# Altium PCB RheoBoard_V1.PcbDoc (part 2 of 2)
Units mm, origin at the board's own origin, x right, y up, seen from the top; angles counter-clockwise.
Board outline 146 x 88.34 mm, 2 copper layers (Top Layer, Bottom Layer); 132 components, 71 nets, 340 pads, 144 vias.
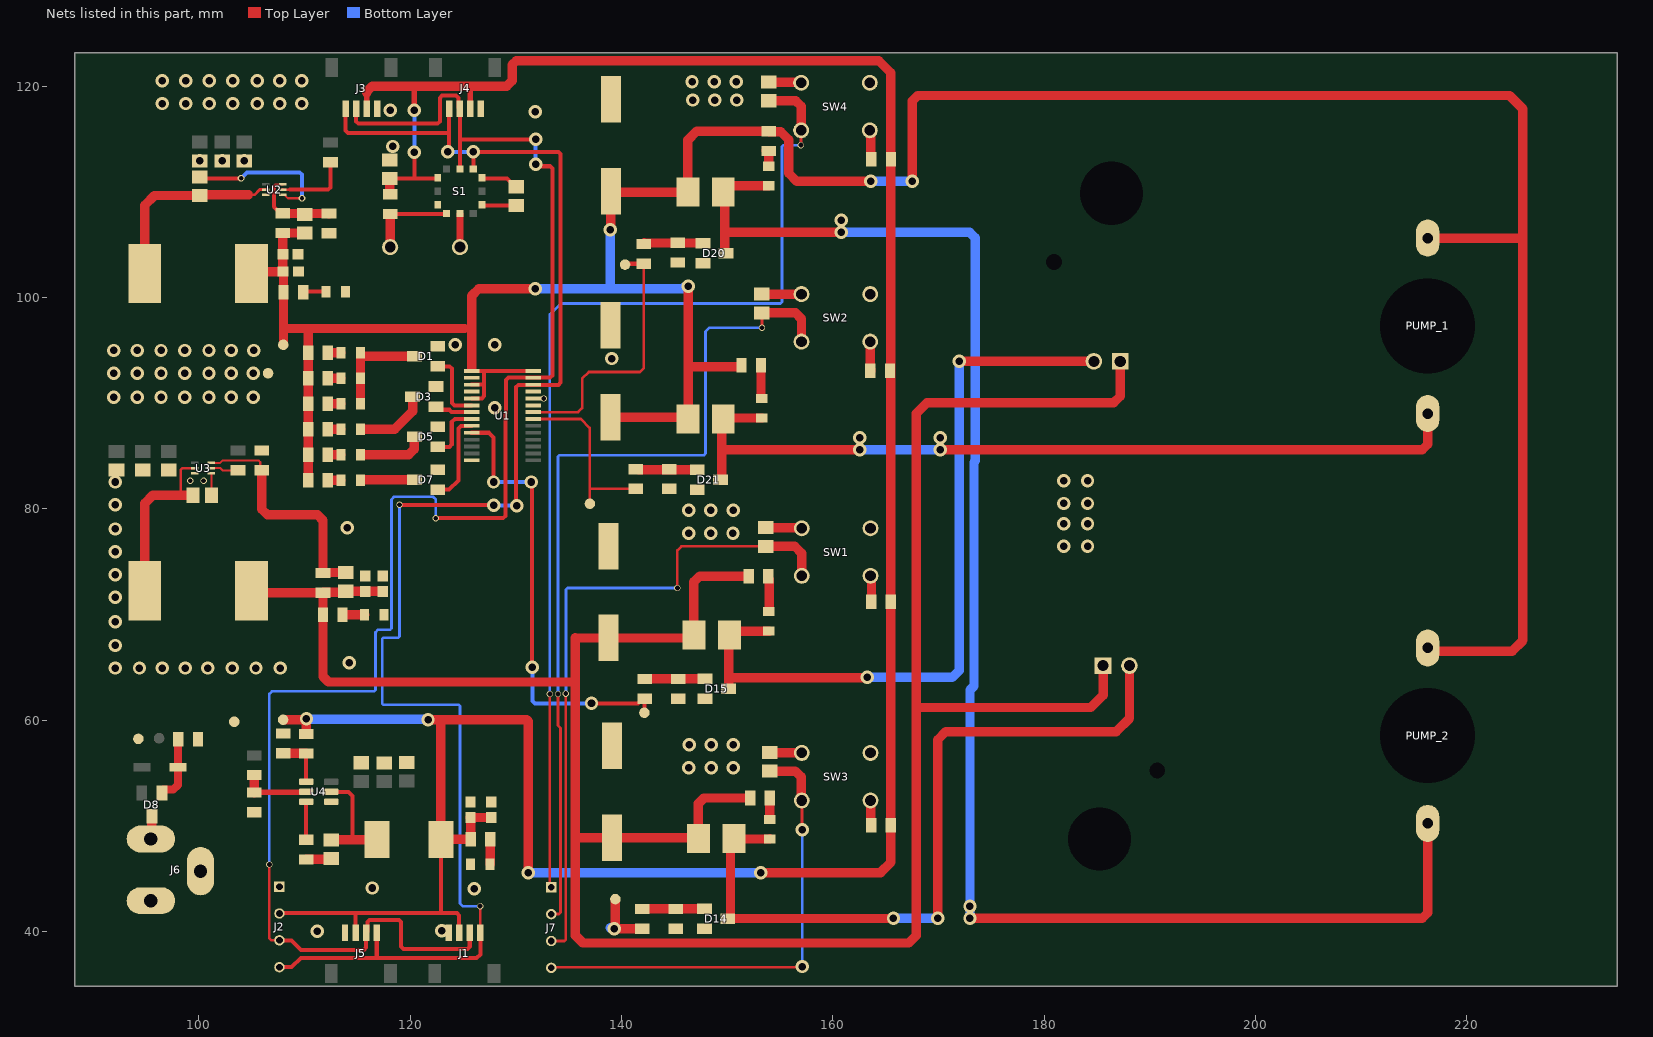
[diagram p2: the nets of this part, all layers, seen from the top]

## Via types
v1: diameter 1.27, hole 0.711, Top Layer to Bottom Layer, tented both sides, 129 vias
v2: diameter 0.6, hole 0.45, Top Layer to Bottom Layer, tented both sides, 13 vias
v3: diameter 0.65, hole 0.4, Top Layer to Bottom Layer, tented both sides, 2 vias

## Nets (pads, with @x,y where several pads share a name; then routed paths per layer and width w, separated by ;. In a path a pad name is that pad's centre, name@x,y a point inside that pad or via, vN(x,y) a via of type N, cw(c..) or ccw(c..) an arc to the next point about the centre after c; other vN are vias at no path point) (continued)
GND: C3.2 C7.1 C8.1 C9.1 C10.1 C11.1 C12.1 C15.1 C16.1 C17.1 C18.1 C22.1 C23.1 C24.1 C25.1 C26.1 C28.2 C29.2 C30.2 C31.2 D1.2 D3.2 D5.2 D7.2 D14.2 D15.2 D20.2 D21.2 GND.1 J1.1 J2.01 J3.1 J4.1 J5.1 J6.2 J6.3 lLED1.1 lLED2.1 lLED3.1 R19.2 R20.1 R27.1 R28.1 R33.1 R34.1 R39.1 R40.1 R41.1 S1.10 SW1.3 SW2.3 SW3.3 SW4.3 U1.2 U1.4 U1.14 U1.23 U1.24 U1.25 U2.3 U3.3 U4.1
  other v1: 111.227,40.03 122.987,40.081 126.06,44.069 116.395,44.133 146.38,55.524 148.476,55.524 150.571,55.524 146.393,57.683 148.488,57.683 150.584,57.683 92.1,64.948 94.386,64.948 96.545,64.948 98.704,64.948 100.863,64.948 103.149,64.948 105.41,64.948 107.696,64.948 114.224,65.43 92.075,67.081 92.075,69.342 92.075,71.628 92.075,73.787 92.075,75.946 181.864,76.454 184.095,76.454 146.355,77.699 148.45,77.699 150.546,77.699 92.075,78.105 114.046,78.232 181.864,78.613 184.095,78.613 146.368,79.858 148.463,79.858 150.558,79.858 92.075,80.391 181.864,80.518 184.095,80.518 92.075,82.55 181.864,82.677 184.095,82.677 127.991,89.586 91.965,90.551 94.196,90.551 96.427,90.551 98.658,90.551 100.965,90.551 103.075,90.551 105.156,90.551 91.965,92.837 94.196,92.837 96.427,92.837 98.658,92.837 100.965,92.837 103.075,92.837 105.156,92.837 139.065,94.234 91.965,94.996 94.196,94.996 96.427,94.996 98.658,94.996 100.965,94.996 103.075,94.996 105.185,94.996 124.282,95.529 127.991,95.529 100.09,112.939 102.2,112.939 104.31,112.939 118.364,114.3 131.826,117.602 118.11,117.729 96.537,118.364 98.768,118.364 100.999,118.364 103.23,118.364 105.537,118.364 107.647,118.364 109.757,118.364 146.723,118.694 148.819,118.694 150.914,118.694 146.672,120.421 148.768,120.421 150.863,120.421 96.537,120.523 98.768,120.523 100.999,120.523 103.23,120.523 105.537,120.523 107.647,120.523 109.757,120.523
  other v2: 99.187,82.677 100.457,82.677 132.639,90.449
Net3V3_1: 3V3.1 C3.1 C25.2 C26.2 J1.2 J2.02 J3.2 J4.2 J5.2 L3.2 R1.2 R2.2 R6.2 R7.2 R8.2 R25.2 R26.2 S1.12 | length 264.4
  Top Layer w0.381: J2.02@107.63,41.72 107.68,41.77 122.86,41.77 ; J5.2@114.84,39.903 114.84,41.656 ; C3.1@118.06,111.265 118.073,111.252 120.396,111.252 ; v1(120.396,113.767) 120.396,111.252 ; S1.12@122.614,111.252 120.396,111.252 ; L3.2@122.92,48.7 122.92,41.83 122.86,41.77 ; J1.2@124.64,39.903 124.64,41.547 124.417,41.77 122.86,41.77
  Top Layer w0.508: J3.2@115.89,117.88 115.89,119.38 ; v1(120.396,117.729) 120.396,119.888 ; J4.2@125.69,117.88 125.69,119.698 ; 130.048,122.555 130.054,122.549 130.054,122.415
  Top Layer w0.889: 3V3.1@107.975,60.046 107.997,60.067 110.122,60.067 v1@110.18,60.124 ; R26.2@110.169,58.709 110.18,58.72 v1@110.18,60.124 ; v1(110.19,60.134) v1@110.18,60.124 ; 115.89,119.38 115.89,119.494 116.411,120.015 129.146,120.015 129.667,120.536 129.667,122.047 130.035,122.415 130.054,122.415 164.35,122.415 165.48,121.285 165.48,113.12 165.487,113.113 165.487,71.237 R1.2@165.48,71.23 R7.2@165.48,50.07 165.48,46.557 164.516,45.593 v1(153.162,45.593) ; R6.2@118.06,109.982 C3.1@118.06,111.265 ; v1(121.691,60.071) 122.936,60.071 ; C25.2@125.67,50.804 125.67,50.769 125.725,50.714 R25.2@125.725,48.731 122.951,48.731 L3.2@122.92,48.7 122.911,48.709 122.911,60.046 122.936,60.071 ; C25.2@125.72,50.804 125.722,50.802 127.669,50.802 C26.2@127.671,50.799 ; v1(131.191,45.593) 131.191,59.893 131.013,60.071 122.936,60.071
  Bottom Layer w0.381: v1(120.396,113.767) v1(120.396,117.729)
  Bottom Layer w0.889: v1(110.19,60.134) 110.222,60.103 v1@121.66,60.103 ; v1(131.191,45.593) v1(153.162,45.593)
Net4V5_1: 4V5.1 C13.2 C15.2 C16.2 C30.1 C31.1 D18.2 D19.2 L1.1 PUMP_1.1 PUMP_2.1 R9.2 R10.2 R11.2 R12.2 R13.1 R14.1 R15.1 R16.2 R35.1 R36.1 U1.1 U1.3 U1.5 U1.28 | length 292.3
  Top Layer w0.381: U1.3@125.824,91.756 126.981,91.756 127.005,91.78 ; U1.1@125.824,93.051 U1.28@131.666,93.051 ; U1.5@125.837,90.473 126.788,90.473 127.005,90.69 127.005,91.78 ; 127.005,92.921 127.005,91.78
  Top Layer w0.889: L1.1@104.98,102.28 105.16,102.46 C16.2@107.964,102.46 ; R16.2@107.96,106.11 107.962,106.108 107.962,102.462 107.978,102.462 108.02,102.419 R12.2@108.02,100.51 108.02,95.549 4V5.1@108.001,95.529 ; R16.2@107.962,106.107 110.008,106.107 C13.2@110.01,106.105 ; 108.153,97.07 110.363,97.07 ; R15.1@110.349,82.72 R14.1@110.349,85.133 R13.1@110.349,87.546 R9.2@110.349,89.959 R10.2@110.349,92.372 R11.2@110.349,94.785 110.349,97.056 110.363,97.07 ; 125.16,97.07 110.363,97.07 ; 125.84,93.3 125.84,100.186 126.492,100.838 v1(131.826,100.838) ; v1(138.938,106.426) 138.969,106.457 138.969,110.014 C30.1@139,110.045 ; C30.1@138.938,109.745 139.175,109.982 D19.2@146.278,109.982 146.278,114.909 147.107,115.738 153.756,115.738 153.797,115.779 153.838,115.738 R35.1@153.924,115.738 153.965,115.698 155.072,115.698 155.829,114.94 155.829,111.76 156.591,110.998 v1(163.576,110.998) ; C31.1@138.94,88.69 146.096,88.69 D18.2@146.278,88.508 ; D18.2@146.304,88.599 v1(146.304,101.092) ; 146.431,93.472 151.302,93.472 151.343,93.513 R36.1@151.343,93.599 ; v1(167.513,110.998) 167.513,118.605 168.034,119.126 224.028,119.126 225.298,117.856 225.298,105.537 ; PUMP_2.1@216.281,66.847 216.58,66.548 224.282,66.548 225.298,67.564 225.298,105.537 ; PUMP_1.1@216.281,105.627 225.208,105.627 225.298,105.537
  Bottom Layer w0.889: v1(131.826,100.838) 145.82,100.838 146.001,101.019 146.231,101.019 v1(146.304,101.092) ; 138.938,100.838 v1(138.938,106.426) ; v1(163.576,110.998) v1(167.513,110.998)
NetC1_1: C1.1 SW1.4 | length 3.4
  Top Layer w0.889: C1.1@153.64,78.235 153.673,78.203 157.027,78.203 SW1.4@157.06,78.17
NetC2_1: C2.1 SW2.4 | length 3.7
  Top Layer w0.889: C2.1@153.289,100.326 153.292,100.329 157.028,100.329 SW2.4@157.031,100.332
NetC4_1: C4.1 S1.6 | length 3.2
  Top Layer w0.381: S1.6@126.814,108.712 130.044,108.712 C4.1@130.048,108.716
NetC4_2: C4.2 S1.4 | length 3.6
  Top Layer w0.381: S1.4@126.814,111.252 129.167,111.252 129.933,110.486 C4.2@130.048,110.486
NetC5_1: C5.1 SW3.4 | length 3
  Top Layer w0.889: C5.1@154.035,56.955 154.055,56.935 157.04,56.935 SW3.4@157.06,56.915
NetC6_1: C6.1 SW4.4 | length 3.1
  Top Layer w0.889: C6.1@153.924,120.392 153.957,120.359 156.965,120.359 SW4.4@156.998,120.326
NetC13_1: C13.1 R16.1 R19.1 U2.6 | length 10.6
  Top Layer w0.203: 107.13,110.3 107.13,110.588 107.249,110.707 107.917,110.707 U2.6@107.93,110.72
  Top Layer w0.381: 107.13,110.3 107.13,108.595 107.755,107.97 R16.1@107.96,107.97 ; C13.1@110.01,107.91 112.25,107.91 R19.1@112.31,107.85
  Top Layer w0.889: R16.1@107.96,107.97 107.97,107.96 112.31,107.96 R19.1@112.32,107.95
NetC14_1: C14.1 R18.1 R20.2 U3.6 | length 22.6
  Top Layer w0.203: U3.6@101.2,84.36 102.02,84.36 102.23,84.57 105.67,84.57 105.81,84.43 105.81,83.82 R20.2@105.96,83.67
  Top Layer w0.889: R20.2@105.96,83.67 105.96,79.98 106.499,79.441 111.233,79.441 111.754,78.92 R18.1@111.754,73.94 111.959,73.94 112.004,73.985 C14.1@113.896,73.985
NetC14_2: C14.2 C17.2 C18.2 C28.1 C29.1 D12.2 D13.2 J8.1 J9.1 L2.1 R17.2 R18.2 R29.1 R30.1 | length 240.9
  Top Layer w0.889: L2.1@104.98,72.08 R18.2@111.754,72.08 ; C18.2@117.4,72.184 117.39,72.194 115.75,72.194 C17.2@115.74,72.204 115.735,72.209 113.901,72.209 C14.2@113.896,72.215 113.801,72.12 111.795,72.12 R18.2@111.754,72.08 ; 135.509,63.627 112.271,63.627 111.75,64.148 R17.2@111.75,70 111.752,70.002 111.752,72.078 R18.2@111.754,72.08 ; R30.1@152.03,73.64 147.39,73.64 146.854,73.104 D12.2@146.854,68.07 146.574,67.79 C28.1@138.75,67.79 135.664,67.79 135.636,67.818 135.636,48.89 ; R29.1@152.175,52.645 152.14,52.645 152.134,52.65 147.799,52.65 147.279,52.129 D13.2@147.279,48.835 147.224,48.89 C29.1@139.08,48.89 135.636,48.89 ; J9.1@185.567,65.168 185.567,62.377 184.404,61.214 167.894,61.214 ; J8.1@187.191,93.963 187.191,90.671 186.563,90.043 168.91,90.043 167.894,89.027 167.894,61.214 ; 135.636,48.89 135.636,39.637 136.347,38.925 167.183,38.925 167.894,39.637 167.894,61.214
NetC19_1: C19.1 L1.2 U2.2 | length 18.5
  Top Layer w0.254: 104.7,109.72 105.27,109.72 105.77,110.22 U2.2@106.33,110.22
  Top Layer w0.889: L1.2@94.88,102.28 94.88,108.73 95.805,109.655 C19.1@100.1,109.655 100.165,109.72 104.7,109.72
NetC19_2: C19.2 U2.4 | length 14.3
  Top Layer w0.203: U2.4@107.93,109.72 108.171,109.72 108.184,109.707 108.184,109.646 108.43,109.4 v3(109.76,109.4)
  Top Layer w0.381: C19.2@100.1,111.425 100.235,111.29 v3(104.01,111.29)
  Bottom Layer w0.381: v3(104.01,111.29) 104.57,111.85 109.537,111.85 109.76,111.627 v3(109.76,109.4)
NetC20_1: C20.1 L2.2 U3.2 | length 16.9
  Top Layer w0.254: 98.298,81.28 98.298,83.711 98.447,83.86 U3.2@99.6,83.86
  Top Layer w0.889: L2.2@94.88,72.263 94.88,80.529 95.631,81.28 98.298,81.28 C20.1@99.445,81.28
NetC20_2: C20.2 U3.4 | length 2.1
  Top Layer w0.203: U3.4@101.2,83.36 U3.4@101.2,83.36 101.215,83.347 C20.2@101.215,81.28
NetC21_1: C21.1 L3.1 U4.2 | length 10.7
  Top Layer w0.381: U4.2@112.535,53.235 114.155,53.235 114.56,52.83 114.56,48.823 114.697,48.685
  Top Layer w0.889: C21.1@112.54,48.685 114.697,48.685 116.855,48.685 L3.1@116.87,48.7
NetC21_2: C21.2 R21.2 | length 2.4
  Top Layer w0.889: R21.2@110.15,46.83 110.191,46.871 112.496,46.871 C21.2@112.54,46.915
NetD1_1: D1.1 U1.6 | length 6.6
  Top Layer w0.381: D1.1@122.605,93.495 123.727,93.495 123.95,93.272 123.95,90.04 124.19,89.8 U1.6@125.824,89.8
NetD1_3: D1.3 LED1.1 LED2.1 LED3.1 | length 10
  Top Layer w0.889: LED1.1@115.305,89.965 LED2.1@115.305,92.378 LED3.1@115.305,94.705 ; LED3.1@115.305,94.791 LED3.1@115.305,94.705 ; D1.3@120.405,94.445 115.566,94.445 LED3.1@115.305,94.705
NetD3_1: D3.1 U1.7 | length 3.6
  Top Layer w0.381: D3.1@122.435,89.685 122.734,89.386 123.707,89.386 123.932,89.16 125.819,89.16 U1.7@125.824,89.165
NetD3_3: D3.3 LED4.1 | length 7.2
  Top Layer w0.889: LED4.1@115.305,87.552 118.54,87.552 120.235,89.247 D3.3@120.235,90.635 120.14,90.635 D3.3@120.085,90.579
NetD5_1: D5.1 U1.8 | length 5.5
  Top Layer w0.381: D5.1@122.605,85.875 123.712,85.875 123.935,86.098 123.935,88.215 124.225,88.505 U1.8@125.824,88.505
NetD5_3: D5.3 LED5.1 | length 6.7
  Top Layer w0.889: LED5.1@115.305,85.139 119.875,85.139 120.396,85.66 120.396,86.816 D5.3@120.405,86.825 D5.3@120.205,86.825
NetD7_1: D7.1 U1.9 | length 8.6
  Top Layer w0.381: D7.1@122.61,81.82 123.68,81.82 124.57,82.71 124.57,87.634 124.793,87.857 U1.9@125.811,87.857
NetD7_3: D7.3 LED6.1 | length 5.1
  Top Layer w0.889: LED6.1@115.305,82.726 115.305,82.733 115.321,82.748 120.388,82.748 D7.3@120.41,82.77
NetD8_1: D8.1 D9.2 R28.2 | length 6.3
  Top Layer w0.762: D8.1@96.52,53.12 96.52,53.32 96.639,53.439 97.584,53.439 98.03,53.885 D9.2@98.03,55.56 98.045,55.575 98.045,58.195 R28.2@98.06,58.21
NetD8_3: D8.3 J6.1 | length 2.1
  Top Layer w0.762: D8.3@95.563,50.843 D8.3@95.61,50.89
  Top Layer w0.889: J6.1@95.543,48.772 95.543,50.823 D8.3@95.563,50.843
NetD10_1: D10.1 D12.1 D15.3 J8.2 | length 73.1
  Top Layer w0.889: D15.3@150.11,62.99 150.158,63.038 150.158,64.03 ; D10.1@153.97,68.446 150.582,68.446 D12.1@150.206,68.07 150.158,68.022 150.158,64.03 ; v1(163.265,64.065) 163.23,64.03 150.158,64.03 ; v1(171.958,93.98) 171.967,93.971 184.682,93.971 J8.2@184.691,93.963
  Bottom Layer w0.889: v1(163.265,64.065) 171.31,64.065 171.958,64.713 v1(171.958,93.98)
NetD10_2: D10.2 R30.2 | length 3.4
  Top Layer w0.889: R30.2@153.89,73.64 153.89,73.435 153.97,73.355 D10.2@153.97,70.294
NetD11_1: D11.1 D13.1 D14.3 J9.2 | length 72.2
  Top Layer w0.889: D11.1@154.03,48.776 154.024,48.77 150.696,48.77 D13.1@150.631,48.835 150.31,48.514 150.31,41.27 D14.3@150.285,41.245 ; v1(165.735,41.275) 165.705,41.245 D14.3@150.285,41.245 ; v1(169.926,41.275) 169.926,58.166 170.688,58.928 186.817,58.928 188.067,60.178 J9.2@188.067,65.168 ; D14.3@150.285,41.245 150.255,41.215 D14.3@150.055,41.215 150.085,41.245 D14.3@150.285,41.245
  Bottom Layer w0.889: v1(165.735,41.275) v1(169.926,41.275)
NetD11_2: D11.2 R29.2 | length 2
  Top Layer w0.889: D11.2@154.03,50.624 154.033,50.627 154.033,52.643 R29.2@154.035,52.645
NetD14_1: D14.1 R31.2 R33.2 | length 5.9
  Top Layer w0.889: R31.2@141.97,42.145 141.98,42.155 147.845,42.155 D14.1@147.855,42.165
NetD15_1: D15.1 R32.2 R34.2 | length 5.7
  Top Layer w0.889: R32.2@142.195,63.9 142.215,63.92 147.89,63.92 D15.1@147.91,63.94
NetD16_1: D16.1 D18.1 D21.3 PUMP_1.2 | length 79.5
  Top Layer w0.889: D21.3@149.373,82.748 D21.3@149.446,82.748 ; D21.3@149.456,82.738 D21.3@149.446,82.748 ; D16.1@153.289,88.611 149.733,88.611 D18.1@149.63,88.508 149.502,88.379 149.502,85.591 ; v1(162.56,85.598) 149.508,85.598 149.502,85.591 ; v1(170.18,85.598) 215.76,85.598 216.281,86.119 PUMP_1.2@216.281,89.027 ; D21.3@149.446,82.748 149.502,82.804 149.502,85.591
  Bottom Layer w0.889: v1(162.56,85.598) v1(170.18,85.598)
  other v1: 162.56,86.741 170.18,86.741
NetD16_2: D16.2 R36.2 | length 3.2
  Top Layer w0.889: R36.2@153.203,93.599 153.203,90.475 153.218,90.459 D16.2@153.289,90.459
NetD17_1: D17.1 D19.1 D20.3 PUMP_2.2 | length 151
  Top Layer w0.889: D20.3@149.898,104.196 149.82,104.196 149.764,104.251 149.764,106.172 ; D17.1@153.924,110.582 150.23,110.582 D19.1@149.63,109.982 149.764,109.848 149.764,106.172 ; v1(160.782,106.172) 149.764,106.172 ; v1(172.974,41.275) 215.76,41.275 216.281,41.796 PUMP_2.2@216.281,50.247
  Bottom Layer w0.889: v1(160.782,106.172) 172.961,106.172 173.482,105.651 173.482,84.564 173.355,84.437 173.355,63.246 172.974,62.865 v1(172.974,41.275)
  other v1: 172.974,42.418 160.782,107.315
NetD17_2: D17.2 R35.2 | length 1.7
  Top Layer w0.889: R35.2@153.678,113.919 153.719,113.878 R35.2@153.924,113.878 D17.2@153.924,112.43
NetD20_1: D20.1 R37.2 R39.2 | length 5.6
  Top Layer w0.889: R37.2@142.147,105.18 142.164,105.163 145.322,105.163 147.681,105.163 D20.1@147.698,105.146
NetD21_1: D21.1 R38.2 R40.2 | length 5.8
  Top Layer w0.889: R38.2@141.361,83.761 141.566,83.761 141.629,83.698 D21.1@147.173,83.698
NetLED1_2: LED1.2 R9.1 | length 1.3
  Top Layer w0.889: R9.1@112.209,89.959 112.212,89.962 113.454,89.962 LED1.2@113.457,89.965
NetLED2_2: LED2.2 R10.1 | length 1.3
  Top Layer w0.889: R10.1@112.209,92.372 112.212,92.375 113.454,92.375 LED2.2@113.457,92.378
NetLED3_2: LED3.2 R11.1 | length 1.3
  Top Layer w0.889: R11.1@112.209,94.785 112.212,94.788 113.454,94.788 LED3.2@113.457,94.791
NetLED4_2: LED4.2 R13.2 | length 1.3
  Top Layer w0.889: R13.2@112.209,87.546 112.212,87.549 113.454,87.549 LED4.2@113.457,87.552
NetLED5_2: LED5.2 R14.2 | length 1.3
  Top Layer w0.889: R14.2@112.209,85.133 112.212,85.136 113.454,85.136 LED5.2@113.457,85.139
NetLED6_2: LED6.2 R15.2 | length 1.3
  Top Layer w0.889: R15.2@112.209,82.72 112.212,82.723 113.454,82.723 LED6.2@113.457,82.726
NetlLED1_2: lLED1.2 R12.1 | length 2.2
  Top Layer w0.381: R12.1@109.88,100.51 109.93,100.56 lLED1.2@112.026,100.56
NetlLED2_2: lLED2.2 R17.1 | length 2.1
  Top Layer w0.889: R17.1@113.61,70 lLED2.2@115.696,70
NetlLED3_2: lLED3.2 R25.1 | length 2.3
  Top Layer w0.889: lLED3.2@127.574,46.4 127.58,46.405 127.58,48.726 R25.1@127.585,48.731
NetPUMP1_1: PUMP1.1 R38.1 U1.21 | length 17.2
  Top Layer w0.254: U1.21@131.666,88.505 136.158,88.505 136.982,87.681 136.982,81.915 ; PUMP1.1@137.008,80.493 136.982,80.518 136.982,81.915 ; R38.1@141.361,81.901 141.347,81.915 136.982,81.915
NetPUMP2_1: PUMP2.1 R37.1 U1.22 | length 25.2
  Top Layer w0.254: U1.22@131.666,89.165 131.672,89.16 135.896,89.16 136.271,89.535 136.271,92.329 136.906,92.964 141.732,92.964 142.113,93.345 R37.1@142.113,103.21
  Top Layer w0.381: PUMP2.1@140.589,103.201 R37.1@142.104,103.201
NetR1_1: R1.1 SW1.1 | length 2.6
  Top Layer w0.889: SW1.1@163.31,73.67 163.364,73.67 163.65,73.384 163.65,71.26 R1.1@163.62,71.23
NetR2_1: R2.1 SW2.1 | length 2.8
  Top Layer w0.889: SW2.1@163.531,95.832 163.531,93.29 163.594,93.227 R2.1@163.594,93.022
NetR6_1: R6.1 S1.9 TP1.TP | length 8.5
  Top Layer w0.381: R6.1@118.11,107.909 118.124,107.895 123.43,107.895 S1.9@123.444,107.882
  Top Layer w0.889: TP1.TP@118.11,104.775 R6.1@118.11,107.909
NetR7_1: R7.1 SW3.1 | length 2.4
  Top Layer w0.889: SW3.1@163.56,52.415 163.59,52.385 163.59,50.1 R7.1@163.62,50.07
NetR8_1: R8.1 SW4.1 | length 2.8
  Top Layer w0.889: SW4.1@163.498,115.826 163.594,115.73 163.594,113.147 R8.1@163.634,113.106
NetR21_1: R21.1 U4.6 | length 3.6
  Top Layer w0.381: R21.1@110.15,48.69 110.165,48.705 U4.6@110.165,52.285
NetR22_1: R22.1 U2.5 | length 7.1
  Top Layer w0.203: 108.557,110.21 108.62,110.21
  Top Layer w0.254: U2.5@107.93,110.22 107.935,110.215 108.444,110.215 ; 108.449,110.21 108.62,110.21
  Top Layer w0.381: 108.62,110.21 112.237,110.21 112.46,110.433 R22.1@112.46,112.81
NetR23_1: R23.1 U3.5 | length 2.6
  Top Layer w0.203: U3.5@101.2,83.86 102.06,83.86 102.28,83.64 103.68,83.64 R23.1@103.71,83.67
NetR24_1: R24.1 R41.2 U4.5 | length 6.6
  Top Layer w0.508: R41.2@105.277,53.201 U4.5@110.141,53.201 ; U4.5@110.141,53.211 U4.5@110.165,53.235
  Top Layer w0.762: R24.1@105.25,54.81 R24.1@105.26,54.82
  Top Layer w0.889: R41.2@105.239,53.163 105.25,53.174 R24.1@105.25,54.81
NetR26_1: R26.1 R27.2 U4.4 | length 4.8
  Top Layer w0.381: U4.4@110.165,54.185 110.165,56.845 R26.1@110.169,56.849
  Top Layer w0.889: R27.2@108,56.88 108.016,56.864 110.154,56.864 R26.1@110.169,56.849
NetR31_1: R31.1 VALE2.1 | length 6
  Top Layer w0.889: v1(139.313,40.259) 139.313,40.362 139.421,40.469 VALE2.1@139.421,43.078 ; v1@139.339,40.285 139.352,40.272 141.957,40.272 R31.1@141.97,40.285
  Bottom Layer w0.889: v1@138.917,40.386 138.971,40.332 139.24,40.332 v1(139.313,40.259)
NetR32_1: R32.1 U1.10 VALE1.1 | length 43.1
  Top Layer w0.381: U1.10@125.824,87.209 127.451,87.209 127.889,86.772 v1(127.889,82.55) ; v1(131.445,82.55) 131.508,82.486 131.508,65.087 v1(131.572,65.024) ; v1(137.16,61.595) 141.545,61.595 141.99,62.04 R32.1@142.195,62.04 ; VALE1.1@142.164,60.719 R32.1@142.164,62.071
  Bottom Layer w0.381: v1(127.889,82.55) v1(131.445,82.55) ; v1(131.572,65.024) 131.572,61.818 131.795,61.595 v1(137.16,61.595)
NetS1_8: S1.8 TP2.TP | length 3.1
  Top Layer w0.635: TP2.TP@124.714,104.775 S1.8@124.714,107.882
PUMP1_IN: C2.2 J7.02 SW2.2 | length 82.7
  Top Layer w0.254: J7.02@133.35,41.656 133.372,41.678 134.075,41.678 134.224,41.827 134.224,59.266 133.985,59.505 v2(133.985,62.484) ; v2(153.289,97.155) C2.2@153.289,98.556
  Top Layer w0.889: C2.2@153.289,98.556 156.46,98.556 157.031,97.985 SW2.2@157.031,95.832
  Bottom Layer w0.254: v2@133.985,62.611 133.985,84.941 134.134,85.09 147.806,85.09 147.955,85.239 147.955,96.774 148.336,97.155 v2(153.289,97.155)
PUMP2_IN: C6.2 J7.01 SW4.2 | length 100.2
  Top Layer w0.254: v2(133.223,62.484) 133.223,44.323 J7.01@133.35,44.196 ; v2(156.972,114.427) 156.985,114.44 156.985,115.813 SW4.2@156.998,115.826
  Top Layer w0.889: C6.2@153.924,118.622 156.477,118.622 156.998,118.101 SW4.2@156.998,115.826
  Bottom Layer w0.254: v2(133.223,62.484) 133.223,98.403 134.261,99.441 155.045,99.441 155.194,99.59 155.194,114.278 155.343,114.427 v2(156.972,114.427)
SCL: J1.4 J2.04 J3.4 J4.4 J5.4 S1.3 U1.26 | length 151.9
  Top Layer w0.203: v2(126.619,42.418) v2@126.63,42.407 ; J1.4@126.63,39.914 J1.4@126.64,39.903
  Top Layer w0.254: J1.4@126.63,39.914 v2@126.63,42.407
  Top Layer w0.381: J2.04@107.63,36.64 108.776,36.64 109.656,37.52 116.83,37.52 ; J3.4@113.89,117.88 113.89,115.793 114.113,115.57 123.69,115.57 ; J5.4@116.84,39.903 116.84,37.53 116.83,37.52 ; v2(118.999,80.391) 127.864,80.391 v1(127.914,80.34) ; v1(123.571,113.792) 123.69,113.911 123.69,115.57 ; J4.4@123.69,117.88 123.69,115.57 ; S1.3@125.984,112.082 v1(125.984,113.792) 134.016,113.792 134.239,113.569 134.239,91.966 134.016,91.743 U1.26@131.679,91.743 ; J1.4@126.64,39.903 126.64,37.86 126.3,37.52 116.83,37.52 ; v1(130.092,80.308) 130.023,80.378 130.023,91.52 130.246,91.743 U1.26@131.653,91.743
  Bottom Layer w0.254: v2(118.999,80.391) 118.999,67.937 118.88,67.818 117.467,67.818 117.348,67.699 117.348,61.595 117.475,61.468 124.595,61.468 124.714,61.349 124.714,42.672 124.968,42.418 v2(126.619,42.418)
  Bottom Layer w0.381: v1(123.571,113.792) v1(125.984,113.792) ; v1(127.914,80.34) 127.93,80.324 130.077,80.324 v1(130.092,80.308)
SDA: J1.3 J2.03 J3.3 J4.3 J5.3 S1.2 U1.27 | length 160
  Top Layer w0.254: v2(106.68,46.355) 106.68,39.37 106.87,39.18 J2.03@107.63,39.18
  Top Layer w0.381: J2.03@107.63,39.18 108.775,39.18 109.685,38.27 115.617,38.27 115.84,38.493 J5.3@115.84,39.903 115.949,40.013 115.949,40.9 116.173,41.123 118.927,41.123 119.15,40.9 119.15,38.593 119.373,38.37 125.417,38.37 125.64,38.593 J1.3@125.64,39.903 ; J3.3@114.89,117.88 114.89,116.682 115.113,116.459 122.586,116.459 122.809,116.682 122.809,118.903 123.032,119.126 124.357,119.126 124.581,118.903 124.581,117.989 J4.3@124.69,117.88 124.702,117.868 124.702,114.981 ; v2(122.428,79.121) 123.337,79.121 128.79,79.121 129.013,79.344 129.013,89.082 129.07,89.139 129.07,92.181 129.306,92.416 U1.27@131.666,92.416 133.254,92.416 133.477,92.64 133.477,112.205 133.254,112.428 132.047,112.428 v1(131.877,112.598) ; S1.2@124.714,112.082 124.702,112.094 124.702,114.981 ; v1(131.877,114.986) 131.872,114.981 124.702,114.981
  Bottom Layer w0.254: v2(106.68,46.355) 106.68,62.484 106.934,62.738 116.564,62.738 116.713,62.887 116.713,68.326 116.967,68.58 118.11,68.58 118.237,68.707 118.237,80.899 118.491,81.153 122.174,81.153 122.428,80.899 v2(122.428,79.121)
  Bottom Layer w0.381: v1(131.877,112.598) v1(131.877,114.986)
VALE1_IN: C1.2 J7.03 SW1.2 | length 63
  Top Layer w0.254: J7.03@133.35,39.116 134.586,39.116 134.734,39.265 v2(134.734,62.529) ; v2(145.288,72.517) 145.288,76.073 145.68,76.465 C1.2@153.64,76.465
  Top Layer w0.889: C1.2@153.64,76.465 156.389,76.465 157.06,75.794 SW1.2@157.06,73.67
  Bottom Layer w0.254: v2(134.734,62.529) 134.747,62.542 134.747,72.368 134.896,72.517 v2(145.288,72.517)
VALE2_IN: C5.2 J7.04 SW3.2 | length 45.1
  Top Layer w0.203: C5.2@153.975,55.245 C5.2@154.035,55.185
  Top Layer w0.254: J7.04@133.35,36.576 133.413,36.639 157.035,36.639 v1(157.099,36.703) ; SW3.2@157.06,52.415 157.079,52.395 157.079,49.677 v1(157.099,49.657)
  Top Layer w0.889: C5.2@154.035,55.185 156.455,55.185 156.99,54.65 156.99,52.485 SW3.2@157.06,52.415
  Bottom Layer w0.254: v1(157.099,36.703) v1(157.099,49.657)
pads on no net: J1.S1 J1.S2 J3.S1 J3.S2 J4.S1 J4.S2 J5.S1 J5.S2 PUMP_1.3 PUMP_2.3 S1.1 S1.5 S1.7 S1.11 U1.11 U1.12 U1.13 U1.15 U1.16 U1.17 U1.18 U1.19 U1.20 VALE_1.4 VALE_2.4

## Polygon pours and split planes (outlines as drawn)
GND on Top Layer "GND_L01_P058" (solid, pour order 58): 137.566,101.308 136.296,100.038 136.296,82.893 138.074,81.115 164.998,81.115 166.776,82.893 166.776,100.038 165.506,101.308
GND on Top Layer "GND_L01_P053" (solid, pour order 53): 110.744,97.282 109.347,95.885 109.347,81.915 110.617,80.645 132.08,80.645 133.35,81.915 133.35,95.885 131.953,97.282
GND on Top Layer "GND_L01_P052" (solid, pour order 52): 90.17,122.555 88.9,121.285 88.9,36.195 89.535,35.56 108.585,35.56 109.22,36.195 109.22,42.418 110.236,43.434 128.016,43.434 132.461,47.879 132.461,77.724 130.937,79.248 109.601,79.248 108.077,80.772 108.077,97.409 109.093,98.425 113.157,98.425 114.554,99.822 114.554,114.681 113.03,116.205 111.76,116.205 111.125,116.84 111.125,121.92 110.49,122.555
GND on Top Layer "GND_L01_P050" (solid, pour order 50): 127,41.618 127.279,41.338 131.445,41.338 131.445,45.212 127.47,45.212 127,44.742
GND on Top Layer "GND_L01_P016" (solid, pour order 16): 110.49,35.052 109.982,35.56 109.982,42.164 110.49,42.672 131.445,42.672 131.445,35.814 130.683,35.052
GND on Top Layer "GND_L01_P059" (solid, pour order 59): 137.732,80.623 136.462,79.353 136.462,62.208 138.24,60.43 165.164,60.43 166.942,62.208 166.942,79.353 165.672,80.623
GND on Top Layer "GND_L01_P077" (solid, pour order 77): 159.385,58.737 159.512,58.61 160.655,58.61 160.782,58.737 160.782,62.166 160.655,62.293 159.512,62.293 159.385,62.166
GND on Top Layer "GND_L01_P076" (solid, pour order 76): 159.766,100.266 159.893,100.139 161.036,100.139 161.163,100.266 161.163,103.695 161.036,103.822 159.893,103.822 159.766,103.695
GND on Top Layer "GND_L01_P075" (solid, pour order 75): 160.147,79.566 160.274,79.438 161.417,79.438 161.544,79.566 161.544,82.995 161.417,83.121 160.274,83.121 160.147,82.995
GND on Top Layer "GND_L01_P061" (solid, pour order 61): 232.537,121.92 232.537,36.195 231.902,35.56 165.735,35.56 165.317,35.978 165.317,121.083 166.153,121.92
GND on Top Layer "GND_L01_P056" (solid, pour order 56): 137.587,121.899 136.317,120.629 136.317,103.484 138.095,101.706 165.019,101.706 166.797,103.484 166.797,120.629 165.527,121.899
GND on Top Layer "GND_L01_P074" (solid, pour order 74): 149.479,98.742 149.606,98.615 150.749,98.615 150.876,98.742 150.876,102.171 150.749,102.298 149.606,102.298 149.479,102.171
GND on Top Layer "GND_L01_P054" (solid, pour order 54): 117.602,115.062 116.713,114.173 116.713,99.822 117.983,98.552 131.572,98.552 132.842,99.822 132.842,114.173 131.953,115.062
GND on Top Layer "GND_L01_P060" (solid, pour order 60): 137.885,59.859 136.615,58.589 136.615,36.74 137.795,35.56 165.735,35.56 167.095,36.92 167.095,58.589 165.825,59.859
GND on Top Layer "GND_L01_P028" (solid, pour order 28): 107.442,90.106 107.315,89.98 107.315,88.837 107.442,88.709 110.871,88.709 110.998,88.837 110.998,89.98 110.871,90.106
GND on Top Layer "GND_L01_P062" (solid, pour order 62): 110.49,122.555 140.335,122.555 140.97,121.92 140.97,116.84 140.335,116.205 110.49,116.205
GND on Top Layer "GND_L01_P046" (solid, pour order 46): 115.697,40.576 115.824,40.45 116.967,40.45 117.094,40.576 117.094,44.005 116.967,44.133 115.824,44.133 115.697,44.005
GND on Top Layer "GND_L01_P036" (solid, pour order 36): 117.602,113.474 117.729,113.347 118.872,113.347 118.999,113.474 118.999,116.903 118.872,117.03 117.729,117.03 117.602,116.903
GND on Top Layer "GND_L01_P034" (solid, pour order 34): 129.032,95.694 129.159,95.567 130.302,95.567 130.429,95.694 130.429,99.123 130.302,99.251 129.159,99.251 129.032,99.123
GND on Top Layer "GND_L01_P032" (solid, pour order 32): 114.427,77.915 114.554,77.787 115.697,77.787 115.824,77.915 115.824,81.343 115.697,81.471 114.554,81.471 114.427,81.343
GND on Top Layer "GND_L01_P030" (solid, pour order 30): 113.983,103.378 113.855,103.251 113.855,102.108 113.983,101.981 117.411,101.981 117.538,102.108 117.538,103.251 117.411,103.378
GND on Bottom Layer "GND_L02_P070" (solid, pour order 70): 137.566,101.308 136.296,100.038 136.296,82.893 138.074,81.115 164.998,81.115 166.776,82.893 166.776,100.038 165.506,101.308
GND on Bottom Layer "GND_L02_P078" (solid, pour order 78): 232.537,122.555 232.537,36.195 231.902,35.56 165.735,35.56 165.317,35.978 165.317,121.083 166.788,122.555
GND on Bottom Layer "GND_L02_P066" (solid, pour order 66): 110.744,97.282 109.347,95.885 109.347,81.915 110.617,80.645 132.08,80.645 133.35,81.915 133.35,95.885 131.953,97.282
GND on Bottom Layer "GND_L02_P071" (solid, pour order 71): 137.732,80.623 136.462,79.353 136.462,62.208 138.24,60.43 165.164,60.43 166.942,62.208 166.942,79.353 165.672,80.623
GND on Bottom Layer "GND_L02_P065" (solid, pour order 65): 117.602,115.062 116.713,114.173 116.713,99.822 117.983,98.552 131.572,98.552 132.842,99.822 132.842,114.173 131.953,115.062
GND on Bottom Layer "GND_L02_P069" (solid, pour order 69): 137.587,121.899 136.317,120.629 136.317,103.484 138.095,101.706 165.019,101.706 166.797,103.484 166.797,120.629 165.527,121.899
GND on Bottom Layer "GND_L02_P072" (solid, pour order 72): 137.885,59.859 136.615,58.589 136.615,36.74 137.795,35.56 165.735,35.56 167.095,36.92 167.095,58.589 165.825,59.859
GND on Bottom Layer "GND_L02_P063" (solid, pour order 63): 90.17,122.555 88.9,121.285 88.9,36.195 89.535,35.56 108.585,35.56 109.22,36.195 109.22,42.418 110.236,43.434 128.016,43.434 128.905,44.323 128.905,60.96 128.27,61.595 119.38,61.595 118.11,62.865 118.11,78.105 117.475,78.74 110.109,78.74 108.077,80.772 108.077,97.409 109.093,98.425 113.157,98.425 114.554,99.822 114.554,114.681 113.03,116.205 111.76,116.205 111.125,116.84 111.125,121.92 110.49,122.555
GND on Bottom Layer "GND_L02_P068" (solid, pour order 68): 110.49,35.052 109.982,35.56 109.982,42.164 110.49,42.672 129.032,42.672 129.794,41.91 129.794,36.068 128.778,35.052
GND on Bottom Layer "GND_L02_P064" (solid, pour order 64): 110.49,122.555 140.335,122.555 140.97,121.92 140.97,116.84 140.335,116.205 110.49,116.205
GND on Bottom Layer "GND_L02_P051" (solid, pour order 51): 127.406,41.237 127.533,41.11 128.676,41.11 128.803,41.237 128.803,44.666 128.676,44.793 127.533,44.793 127.406,44.666
GND on Bottom Layer "GND_L02_P047" (solid, pour order 47): 115.697,40.703 115.824,40.576 116.967,40.576 117.094,40.703 117.094,44.133 116.967,44.259 115.824,44.259 115.697,44.133
GND on Bottom Layer "GND_L02_P037" (solid, pour order 37): 117.602,113.474 117.729,113.347 118.872,113.347 118.999,113.474 118.999,116.903 118.872,117.03 117.729,117.03 117.602,116.903
GND on Bottom Layer "GND_L02_P035" (solid, pour order 35): 129.032,95.694 129.159,95.567 130.302,95.567 130.429,95.694 130.429,99.123 130.302,99.251 129.159,99.251 129.032,99.123
GND on Bottom Layer "GND_L02_P033" (solid, pour order 33): 114.427,77.915 114.554,77.787 115.697,77.787 115.824,77.915 115.824,81.343 115.697,81.471 114.554,81.471 114.427,81.343
GND on Bottom Layer "GND_L02_P031" (solid, pour order 31): 113.983,103.378 113.855,103.251 113.855,102.108 113.983,101.981 117.411,101.981 117.538,102.108 117.538,103.251 117.411,103.378
GND on Bottom Layer "GND_L02_P029" (solid, pour order 29): 107.442,90.106 107.315,89.98 107.315,88.837 107.442,88.709 110.871,88.709 110.998,88.837 110.998,89.98 110.871,90.106

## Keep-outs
Keep-Out Layer:
  circle w0.254: c103.886,38.285 r1.796
  circle w0.254: c230.632,119.38 r1.796
  circle w0.254: c229.87,38.862 r1.796
  circle w0.254: c92.685,119.837 r1.796

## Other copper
Top Layer:
  region net NetD16_1: 168.656,87.122 168.91,87.376 171.323,87.376 171.704,86.995 171.704,84.455 171.45,84.201 168.91,84.201 168.656,84.455
  region net NetD16_1: 161.036,87.122 161.29,87.376 163.703,87.376 164.084,86.995 164.084,84.455 163.83,84.201 161.29,84.201 161.036,84.455
  region net NetD17_1: 171.45,42.799 171.704,43.053 174.117,43.053 174.498,42.672 174.498,40.132 174.244,39.878 171.704,39.878 171.45,40.132
  region net NetD17_1: 159.258,107.696 159.512,107.95 161.925,107.95 162.306,107.569 162.306,105.029 162.052,104.775 159.512,104.775 159.258,105.029
  text "RheoBoard_V1" at 189.865,78.481 h5
Bottom Layer:
  region net NetD17_1: 159.258,107.696 159.512,107.95 161.925,107.95 162.306,107.569 162.306,105.029 162.052,104.775 159.512,104.775 159.258,105.029
  region net NetD16_1: 161.036,87.122 161.29,87.376 163.703,87.376 164.084,86.995 164.084,84.455 163.83,84.201 161.29,84.201 161.036,84.455
  region net NetD16_1: 168.656,87.122 168.91,87.376 171.323,87.376 171.704,86.995 171.704,84.455 171.45,84.201 168.91,84.201 168.656,84.455
  region net NetD17_1: 171.45,42.799 171.704,43.053 174.117,43.053 174.498,42.672 174.498,40.132 174.244,39.878 171.704,39.878 171.45,40.132
Multi-Layer:
  lines w0.152: 88.24,34.85 234.244,34.85 234.244,123.19 154.295,123.19 106.965,123.19 88.24,123.19 88.24,34.85

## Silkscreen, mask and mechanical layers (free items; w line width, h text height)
Top Overlay:
  circle w0.254: c229.87,38.862 r1.6
  circle w0.254: c230.632,119.38 r1.6
  circle w0.254: c92.71,119.83 r1.6
  circle w0.254: c103.886,38.285 r1.6
  region: 176.082,101.473 176.082,118.364 196.656,118.364 196.656,101.473
  region: 174.939,40.259 174.939,57.15 195.513,57.15 195.513,40.259
  text "GND" at 109.347,44.078 h0.8
  text "PUMP_IN2" at 128.651,43.819 h0.74
  text "3V3" at 109.347,41.538 h0.8
  text "PUMP_IN1" at 128.651,41.321 h0.74
  text "SDA" at 109.347,38.871 h0.8
  text "VALE_IN1" at 128.652,38.823 h0.74
  text "VALE_IN2" at 128.652,36.326 h0.74
  text "SCL" at 109.474,35.823 h0.8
